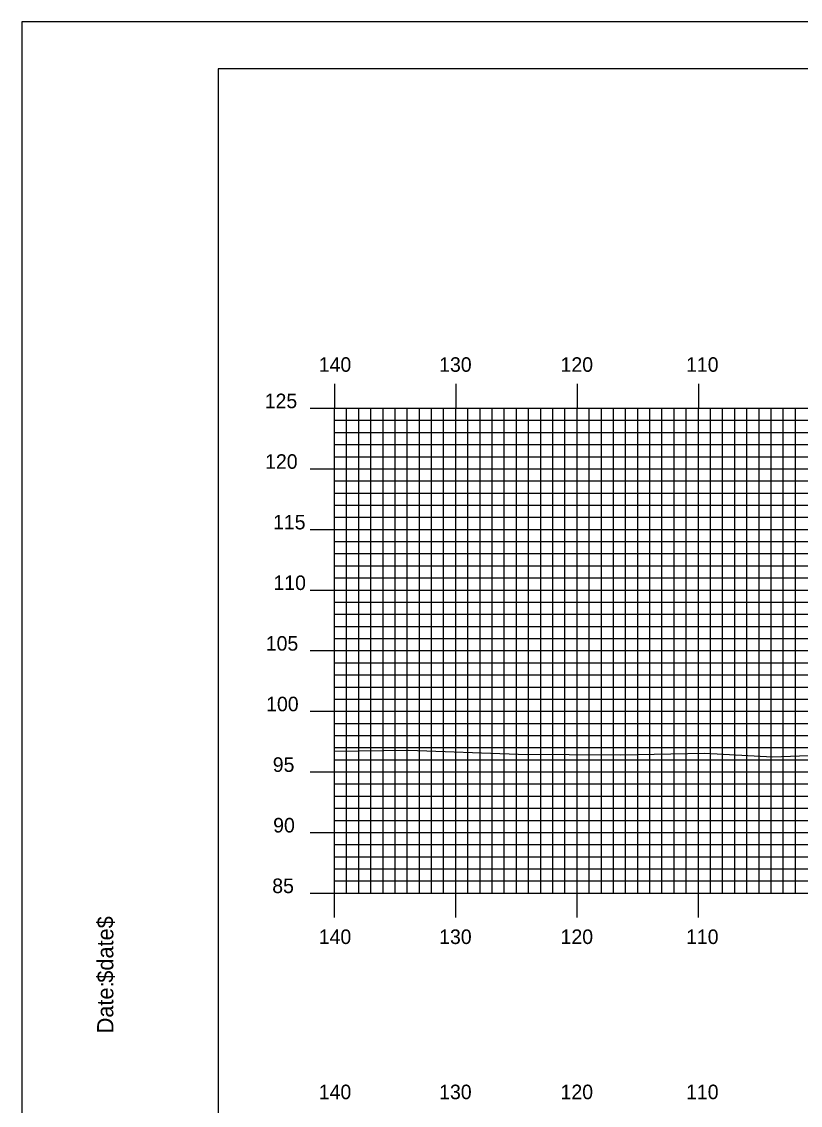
# Model space of a CAD drawing. Extents: x 1786189 to 1786532, y 442591 to 442811.
# Drawn here: x 1786188.8 to 1786253, y 442721.2 to 442810.5 of the extents above; entities that cross this region are included whole.
import ezdxf

# ---------------------------------------------------------------- set-up
doc = ezdxf.new("R2010")
doc.units = 0
for name, color, linetype in [('BORDER', 7, 'Continuous'), ('H_V ANNOTATION', 7, 'Continuous'), ('MAJOR', 7, 'Continuous'), ('MINOR', 7, 'Continuous'), ('PLOT BOUNDARY', 7, 'Continuous'), ('S_Roadway_Centerline', 7, 'Continuous')]:
    doc.layers.add(name, color=color, linetype=linetype)

msp = doc.modelspace()

# ---------------------------------------------------------------- linework, layer by layer
at = {"layer": 'BORDER'}
msp.add_lwpolyline([(1786204.965, 442596.665), (1786524.965, 442596.665), (1786524.965, 442806.665), (1786204.965, 442806.665)], close=True, dxfattribs=at)
at = {"layer": 'MAJOR'}
for p, q in [((1786214.565, 442780.669), (1786214.565, 442778.665)), ((1786224.565, 442780.669), (1786224.565, 442778.665)), ((1786234.565, 442780.669), (1786234.565, 442778.665)), ((1786244.565, 442780.669), (1786244.565, 442778.665)), ((1786212.561, 442778.665), (1786214.565, 442778.665)), ((1786214.565, 442778.665), (1786494.565, 442778.665)), ((1786214.565, 442738.665), (1786214.565, 442778.665)), ((1786214.565, 442738.665), (1786214.565, 442778.665)), ((1786214.565, 442778.665), (1786494.565, 442778.665)), ((1786224.565, 442738.665), (1786224.565, 442778.665)), ((1786234.565, 442738.665), (1786234.565, 442778.665)), ((1786244.565, 442738.665), (1786244.565, 442778.665)), ((1786212.561, 442773.665), (1786214.565, 442773.665)), ((1786214.565, 442773.665), (1786494.565, 442773.665)), ((1786212.561, 442768.665), (1786214.565, 442768.665)), ((1786214.565, 442768.665), (1786494.565, 442768.665)), ((1786212.561, 442763.665), (1786214.565, 442763.665)), ((1786214.565, 442763.665), (1786494.565, 442763.665)), ((1786212.561, 442758.665), (1786214.565, 442758.665)), ((1786214.565, 442758.665), (1786494.565, 442758.665)), ((1786212.561, 442753.665), (1786214.565, 442753.665)), ((1786214.565, 442753.665), (1786494.565, 442753.665)), ((1786212.561, 442748.665), (1786214.565, 442748.665)), ((1786214.565, 442748.665), (1786494.565, 442748.665)), ((1786212.561, 442743.665), (1786214.565, 442743.665)), ((1786214.565, 442743.665), (1786494.565, 442743.665)), ((1786212.561, 442738.665), (1786214.565, 442738.665)), ((1786214.565, 442738.665), (1786494.565, 442738.665)), ((1786214.565, 442738.665), (1786494.565, 442738.665)), ((1786214.565, 442736.661), (1786214.565, 442738.665)), ((1786224.565, 442736.661), (1786224.565, 442738.665)), ((1786234.565, 442736.661), (1786234.565, 442738.665)), ((1786244.565, 442736.661), (1786244.565, 442738.665))]:
    msp.add_line(p, q, dxfattribs=at)
at = {"layer": 'MINOR'}
for p, q in [((1786215.565, 442738.665), (1786215.565, 442778.665)), ((1786216.565, 442738.665), (1786216.565, 442778.665)), ((1786217.565, 442738.665), (1786217.565, 442778.665)), ((1786218.565, 442738.665), (1786218.565, 442778.665)), ((1786219.565, 442738.665), (1786219.565, 442778.665)), ((1786220.565, 442738.665), (1786220.565, 442778.665)), ((1786221.565, 442738.665), (1786221.565, 442778.665)), ((1786222.565, 442738.665), (1786222.565, 442778.665)), ((1786223.565, 442738.665), (1786223.565, 442778.665)), ((1786225.565, 442738.665), (1786225.565, 442778.665)), ((1786226.565, 442738.665), (1786226.565, 442778.665)), ((1786227.565, 442738.665), (1786227.565, 442778.665)), ((1786228.565, 442738.665), (1786228.565, 442778.665)), ((1786229.565, 442738.665), (1786229.565, 442778.665)), ((1786230.565, 442738.665), (1786230.565, 442778.665)), ((1786231.565, 442738.665), (1786231.565, 442778.665)), ((1786232.565, 442738.665), (1786232.565, 442778.665)), ((1786233.565, 442738.665), (1786233.565, 442778.665)), ((1786235.565, 442738.665), (1786235.565, 442778.665)), ((1786236.565, 442738.665), (1786236.565, 442778.665)), ((1786237.565, 442738.665), (1786237.565, 442778.665)), ((1786238.565, 442738.665), (1786238.565, 442778.665)), ((1786239.565, 442738.665), (1786239.565, 442778.665)), ((1786240.565, 442738.665), (1786240.565, 442778.665)), ((1786241.565, 442738.665), (1786241.565, 442778.665)), ((1786242.565, 442738.665), (1786242.565, 442778.665)), ((1786243.565, 442738.665), (1786243.565, 442778.665)), ((1786245.565, 442738.665), (1786245.565, 442778.665)), ((1786246.565, 442738.665), (1786246.565, 442778.665)), ((1786247.565, 442738.665), (1786247.565, 442778.665)), ((1786248.565, 442738.665), (1786248.565, 442778.665)), ((1786249.565, 442738.665), (1786249.565, 442778.665)), ((1786250.565, 442738.665), (1786250.565, 442778.665)), ((1786251.565, 442738.665), (1786251.565, 442778.665)), ((1786252.565, 442738.665), (1786252.565, 442778.665)), ((1786214.565, 442777.665), (1786494.565, 442777.665)), ((1786214.565, 442777.665), (1786216.569, 442777.665)), ((1786214.565, 442776.665), (1786494.565, 442776.665)), ((1786214.565, 442776.665), (1786216.569, 442776.665)), ((1786214.565, 442775.665), (1786494.565, 442775.665)), ((1786214.565, 442775.665), (1786216.569, 442775.665)), ((1786214.565, 442774.665), (1786494.565, 442774.665)), ((1786214.565, 442774.665), (1786216.569, 442774.665)), ((1786214.565, 442772.665), (1786494.565, 442772.665)), ((1786214.565, 442772.665), (1786216.569, 442772.665)), ((1786214.565, 442771.665), (1786494.565, 442771.665)), ((1786214.565, 442771.665), (1786216.569, 442771.665)), ((1786214.565, 442770.665), (1786494.565, 442770.665)), ((1786214.565, 442770.665), (1786216.569, 442770.665)), ((1786214.565, 442769.665), (1786494.565, 442769.665)), ((1786214.565, 442769.665), (1786216.569, 442769.665)), ((1786214.565, 442767.665), (1786494.565, 442767.665)), ((1786214.565, 442767.665), (1786216.569, 442767.665)), ((1786214.565, 442766.665), (1786494.565, 442766.665)), ((1786214.565, 442766.665), (1786216.569, 442766.665)), ((1786214.565, 442765.665), (1786494.565, 442765.665)), ((1786214.565, 442765.665), (1786216.569, 442765.665)), ((1786214.565, 442764.665), (1786494.565, 442764.665)), ((1786214.565, 442764.665), (1786216.569, 442764.665)), ((1786214.565, 442762.665), (1786494.565, 442762.665)), ((1786214.565, 442762.665), (1786216.569, 442762.665)), ((1786214.565, 442761.665), (1786494.565, 442761.665)), ((1786214.565, 442761.665), (1786216.569, 442761.665)), ((1786214.565, 442760.665), (1786494.565, 442760.665)), ((1786214.565, 442760.665), (1786216.569, 442760.665)), ((1786214.565, 442759.665), (1786494.565, 442759.665)), ((1786214.565, 442759.665), (1786216.569, 442759.665)), ((1786214.565, 442757.665), (1786494.565, 442757.665)), ((1786214.565, 442757.665), (1786216.569, 442757.665)), ((1786214.565, 442756.665), (1786494.565, 442756.665)), ((1786214.565, 442756.665), (1786216.569, 442756.665)), ((1786214.565, 442755.665), (1786494.565, 442755.665)), ((1786214.565, 442755.665), (1786216.569, 442755.665)), ((1786214.565, 442754.665), (1786494.565, 442754.665)), ((1786214.565, 442754.665), (1786216.569, 442754.665)), ((1786214.565, 442752.665), (1786494.565, 442752.665)), ((1786214.565, 442752.665), (1786216.569, 442752.665)), ((1786214.565, 442751.665), (1786494.565, 442751.665)), ((1786214.565, 442751.665), (1786216.569, 442751.665)), ((1786214.565, 442750.665), (1786494.565, 442750.665)), ((1786214.565, 442750.665), (1786216.569, 442750.665)), ((1786214.565, 442749.665), (1786494.565, 442749.665)), ((1786214.565, 442749.665), (1786216.569, 442749.665)), ((1786214.565, 442747.665), (1786494.565, 442747.665)), ((1786214.565, 442747.665), (1786216.569, 442747.665)), ((1786214.565, 442746.665), (1786494.565, 442746.665)), ((1786214.565, 442746.665), (1786216.569, 442746.665)), ((1786214.565, 442745.665), (1786494.565, 442745.665)), ((1786214.565, 442745.665), (1786216.569, 442745.665)), ((1786214.565, 442744.665), (1786494.565, 442744.665)), ((1786214.565, 442744.665), (1786216.569, 442744.665)), ((1786214.565, 442742.665), (1786494.565, 442742.665)), ((1786214.565, 442742.665), (1786216.569, 442742.665)), ((1786214.565, 442741.665), (1786494.565, 442741.665)), ((1786214.565, 442741.665), (1786216.569, 442741.665)), ((1786214.565, 442740.665), (1786494.565, 442740.665)), ((1786214.565, 442740.665), (1786216.569, 442740.665)), ((1786214.565, 442739.665), (1786494.565, 442739.665)), ((1786214.565, 442739.665), (1786216.569, 442739.665))]:
    msp.add_line(p, q, dxfattribs=at)
at = {"layer": 'PLOT BOUNDARY'}
msp.add_lwpolyline([(1786188.778, 442590.547), (1786528.778, 442590.547), (1786528.778, 442810.547), (1786188.778, 442810.547)], close=True, dxfattribs=at)
at = {"layer": 'S_Roadway_Centerline'}
msp.add_lwpolyline([(1786214.565, 442750.383), (1786220.669, 442750.444), (1786229.714, 442750.123), (1786238.126, 442750.065), (1786245.105, 442750.197), (1786250.671, 442749.903), (1786256.578, 442750.123), (1786264.831, 442749.396), (1786271.519, 442749.405), (1786286.475, 442748.829), (1786292.164, 442748.871), (1786292.362, 442748.86), (1786292.513, 442748.871), (1786303.513, 442749.131), (1786312.454, 442748.722), (1786315.332, 442748.759), (1786319.67, 442748.522)], dxfattribs=at)

# ---------------------------------------------------------------- texts
at = {"layer": 'BORDER'}
for s, p in [('$date$', (1786196.335, 442731.275)), ('Date:', (1786196.335, 442727.099))]:
    msp.add_text(s, height=1.3392, rotation=90, dxfattribs=at).set_placement(p)
at = {"layer": 'H_V ANNOTATION'}
for s, p in [('140', (1786213.27, 442781.665)), ('130', (1786223.195, 442781.665)), ('120', (1786233.205, 442781.665)), ('110', (1786243.548, 442781.665)), ('125', (1786208.814, 442778.665)), ('120', (1786208.846, 442773.665)), ('115', (1786209.499, 442768.665)), ('110', (1786209.531, 442763.665)), ('105', (1786208.9, 442758.665)), ('100', (1786208.932, 442753.665)), ('95', (1786209.477, 442748.665)), ('90', (1786209.509, 442743.665)), ('85', (1786209.434, 442738.665)), ('140', (1786213.27, 442734.465)), ('130', (1786223.195, 442734.465)), ('120', (1786233.205, 442734.465)), ('110', (1786243.548, 442734.465)), ('140', (1786213.27, 442721.665)), ('130', (1786223.195, 442721.665)), ('120', (1786233.205, 442721.665)), ('110', (1786243.548, 442721.665))]:
    msp.add_text(s, height=1.2, dxfattribs=at).set_placement(p)
at = {"layer": 'MAJOR'}
msp.add_text('-', height=0.012, dxfattribs=at).set_placement((1786214.556, 442738.665))

doc.saveas('drawing.dxf')
